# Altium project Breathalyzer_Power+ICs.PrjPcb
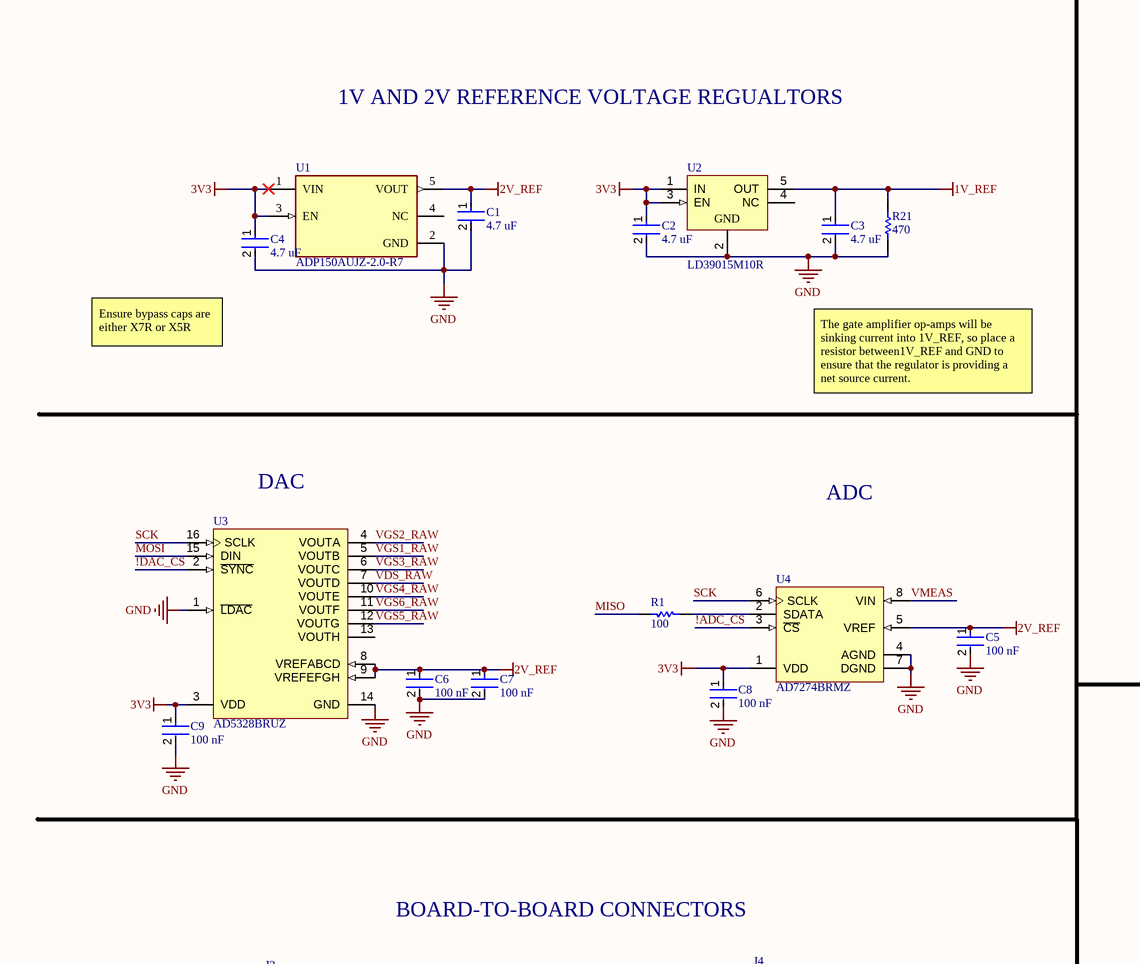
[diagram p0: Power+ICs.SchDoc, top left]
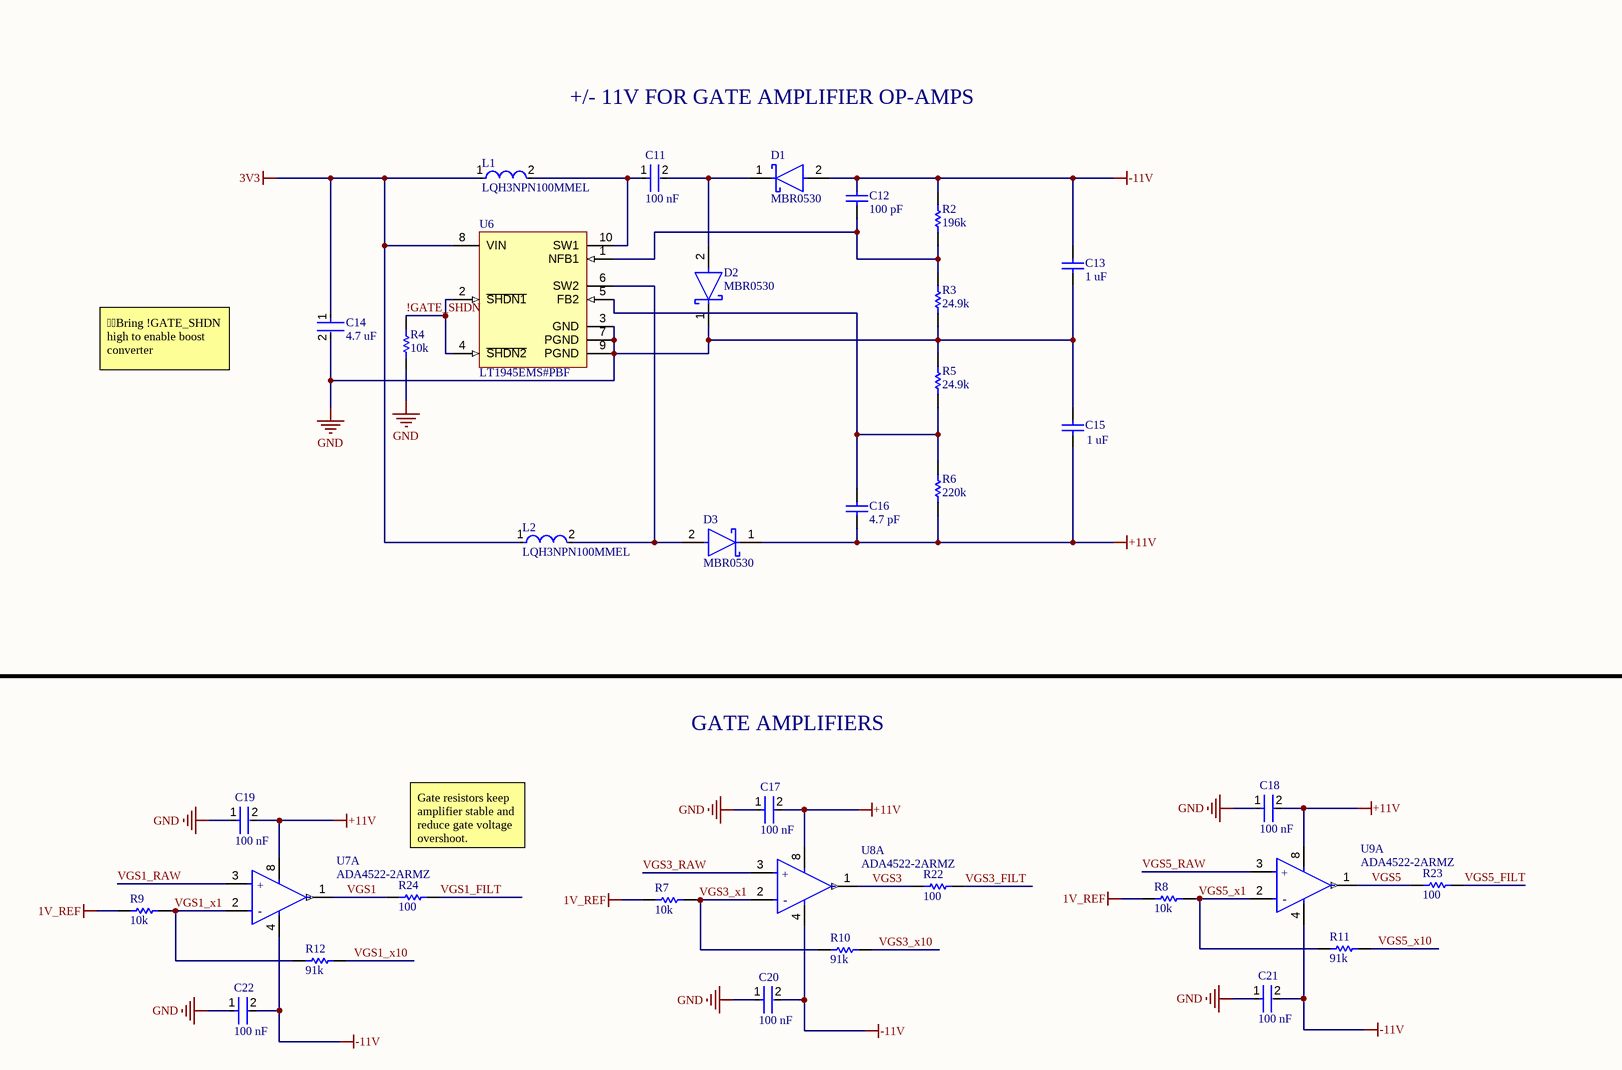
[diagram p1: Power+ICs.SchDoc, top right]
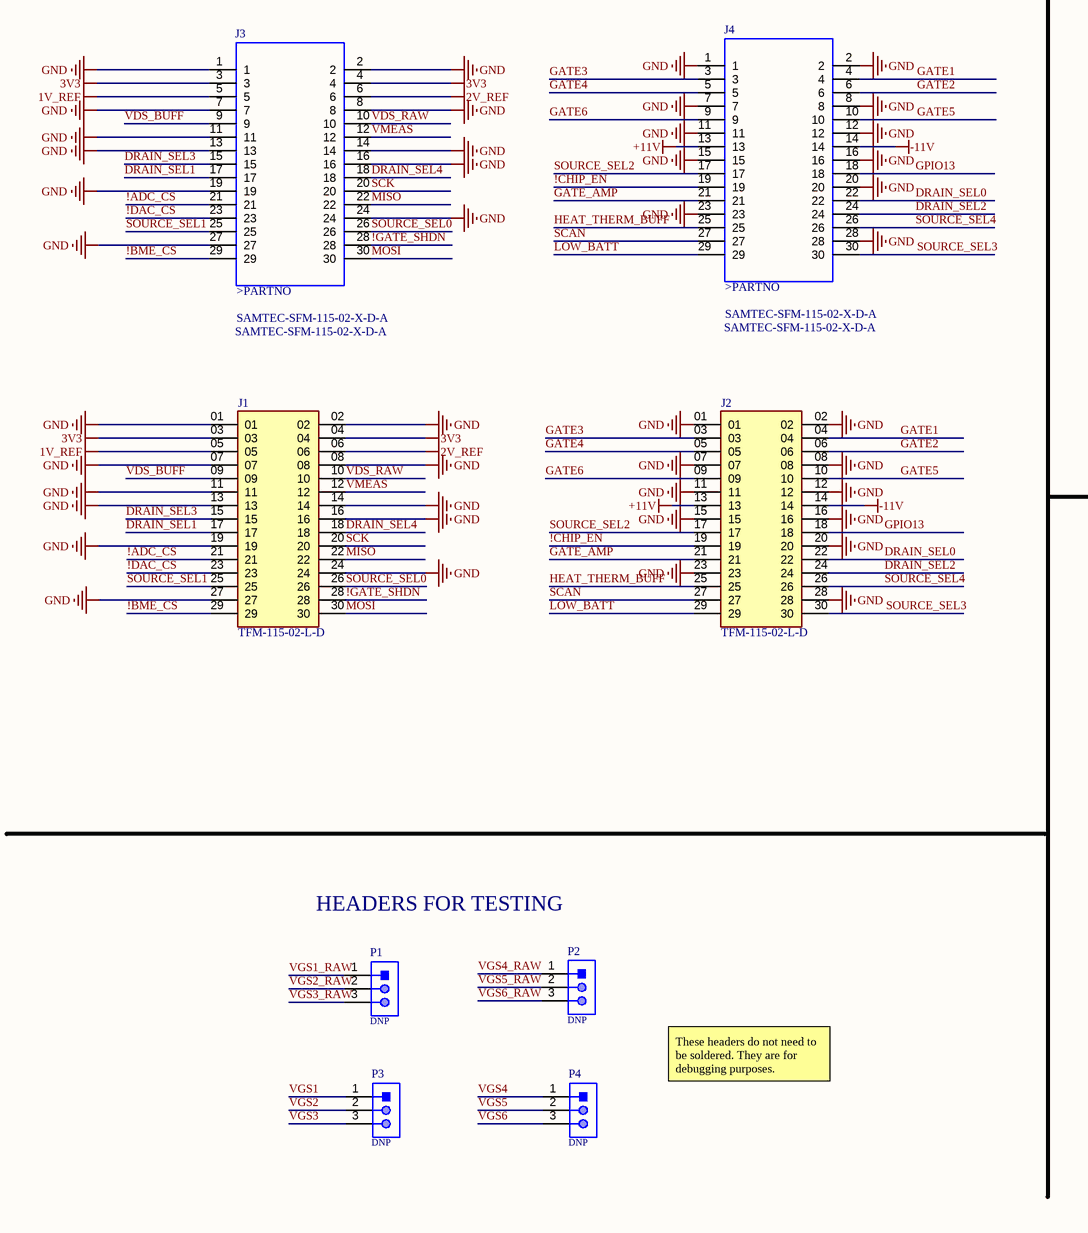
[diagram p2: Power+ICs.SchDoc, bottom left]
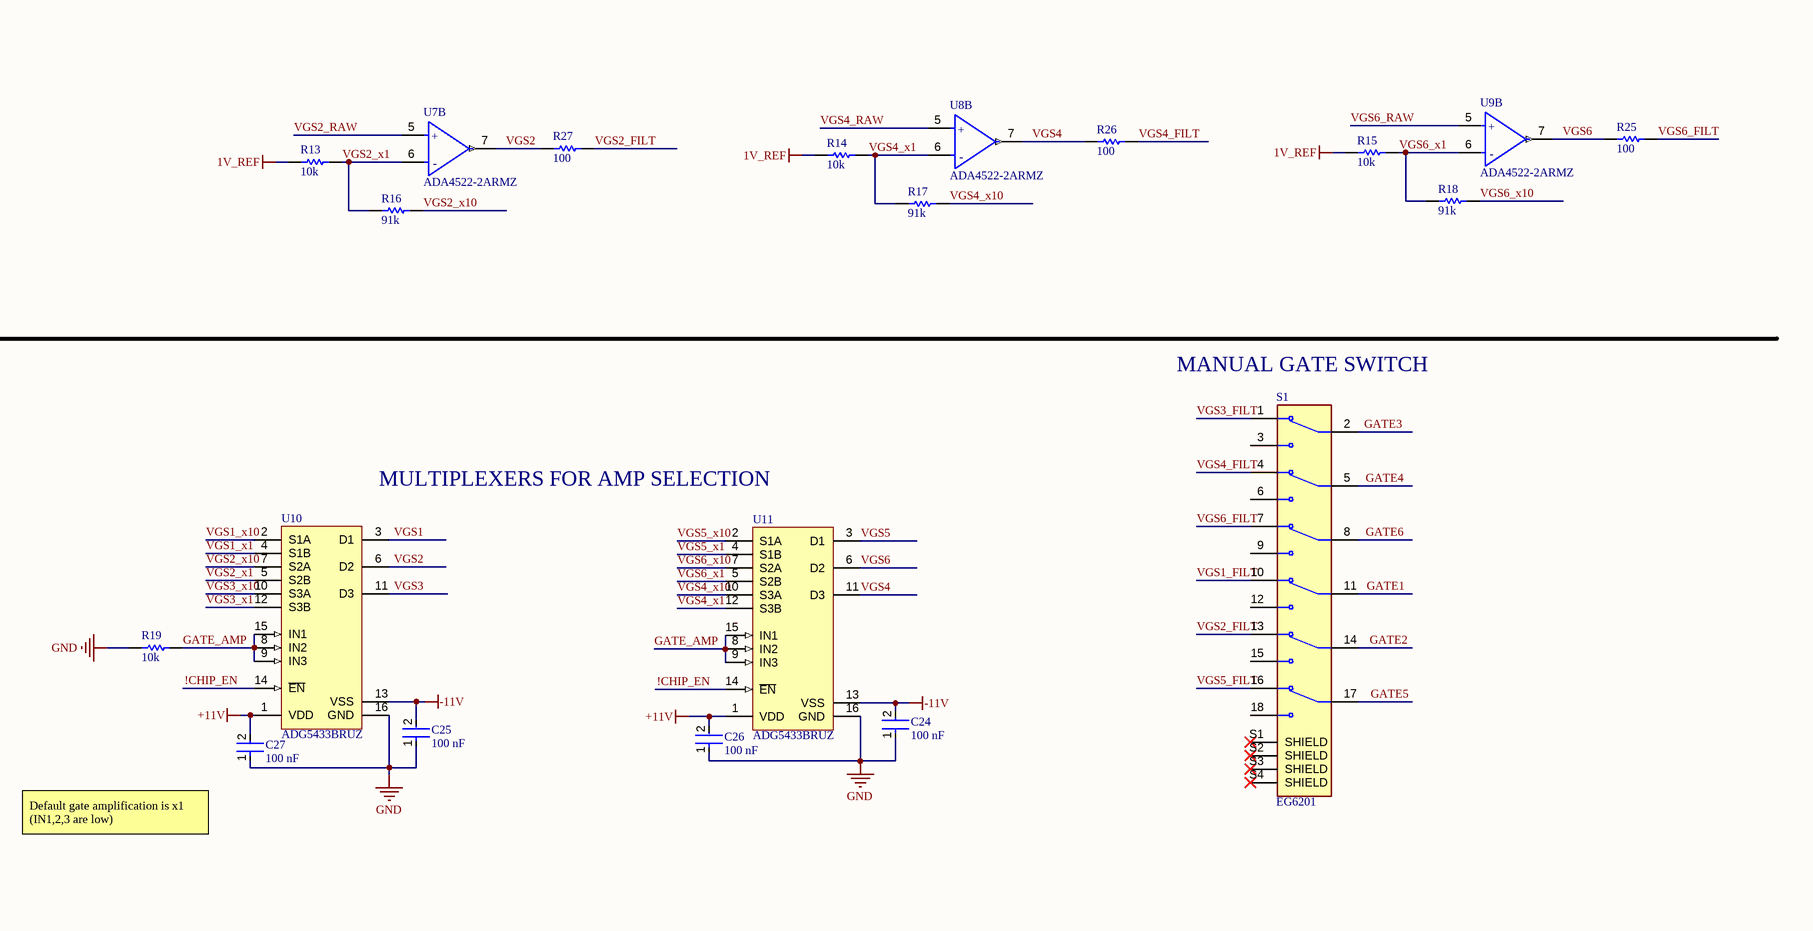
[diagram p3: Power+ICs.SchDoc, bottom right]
CAGE_CODE: ?????; CONTRACT_NUMBER: <CONTRACT NO>; DOC_NO_ASSY_DWG: <ASSY DWG NO>; DOC_NO_BOM: <BOM DOC NO>; DOC_NO_FAB_DWG: <FAB DWG NO>; DOC_NO_SCH_DWG: <SCH DWG NO>; PCB_2_DEC_TOL: +/-.01; PCB_3_DEC_TOL: +/-.010; PCB_ANG_TOL: +/-1/2; PCB_ASSEMBLY_NO: <PCB ASSY NO>; PCB_CHECKER: - -----; PCB_CHECKER_APP_DATE: --/--/----; PCB_DESIGNER: - -----; PCB_DESIGNER_APP_DATE: --/--/----; PCB_DWG_NO: <PCB DWG NO>; PCB_ENGINEER: - -----; PCB_ENGINEER_APP_DATE: --/--/----; PCB_PART_NUMBER: <PCB PN>; PCB_REV: A; SCH_REV: A
1 sheet, 75 parts. Net scope: global (net labels, ports and power ports of the same name join across sheets).
Board file: PCB1.PcbDoc

## Sheet Power+ICs.SchDoc
size 558 x 431 mm; SheetNumber: 1; SheetTotal: 1; ENG_APP_DATE: --/--/--; DSN_APP_DATE: --/--/--; CHK_APP_DATE: --/--/--

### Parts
C1  4.7 uF  [FP-C0805C475K3PACTU-MFG]
C2  4.7 uF  [FP-C0805C475K3PACTU-MFG]
C3  4.7 uF  [FP-C0805C475K3PACTU-MFG]
C4  4.7 uF  [FP-C0805C475K3PACTU-MFG]
C5  100 nF  [FP-C0805C-DN-MFG]
C6  100 nF  [FP-C0805C-DN-MFG]
C7  100 nF  [FP-C0805C-DN-MFG]
C8  100 nF  [FP-C0805C-DN-MFG]
C9  100 nF  [FP-C0805C-DN-MFG]
C11  100 nF  [FP-C0805C-DN-MFG]
C12  100 pF  [CAPC2013X140X50ML20T25]
C13  1 uF  [CAPC3216X110X50LL20T25]
C14  4.7 uF  [FP-C0805C475K3PACTU-MFG]
C15  1 uF  [CAPC3216X110X50LL20T25]
C16  4.7 pF  [CAPC2013X71X50ML20T25]
C17  100 nF  [FP-C0805C-DN-MFG]
C18  100 nF  [FP-C0805C-DN-MFG]
C19  100 nF  [FP-C0805C-DN-MFG]
C20  100 nF  [FP-C0805C-DN-MFG]
C21  100 nF  [FP-C0805C-DN-MFG]
C22  100 nF  [FP-C0805C-DN-MFG]
C24  100 nF  [FP-C0805C-DN-MFG]
C25  100 nF  [FP-C0805C-DN-MFG]
C26  100 nF  [FP-C0805C-DN-MFG]
C27  100 nF  [FP-C0805C-DN-MFG]
D1  MBR0530  [FP-425-04-MFG]
D2  MBR0530  [FP-425-04-MFG]
D3  MBR0530  [FP-425-04-MFG]
J1  TFM-115-02-L-D  [SAMTEC_TFM-115-02-L-D]
J2  TFM-115-02-L-D  [SAMTEC_TFM-115-02-L-D]
J3  SAMTEC-SFM-115-02-X-D-A  [SAMTEC-SFM-115-02-X-D-A]
J4  SAMTEC-SFM-115-02-X-D-A  [SAMTEC-SFM-115-02-X-D-A]
L1  LQH3NPN100MMEL  [FP-LQH3NPH_ME-MFG]
L2  LQH3NPN100MMEL  [FP-LQH3NPH_ME-MFG]
P1  DNP  [61300311021]
P2  DNP  [61300311021]
P3  DNP  [61300311021]
P4  DNP  [61300311021]
R1  100  [RESC2013X50X30LL20T20]
R2  196k  [RESC2013X50X30LL20T20]
R3  24.9k  [RESC2013X70X40LL20T20]
R4  10k  [RESC2013X60X35NL10T20]
R5  24.9k  [RESC2013X70X40LL20T20]
R6  220k  [RESC2013X70X40ML20T20]
R7  10k  [RESC2013X60X35NL10T20]
R8  10k  [RESC2013X60X35NL10T20]
R9  10k  [RESC2013X60X35NL10T20]
R10  91k  [RESC2013X60X35ML10T20]
R11  91k  [RESC2013X60X35ML10T20]
R12  91k  [RESC2013X60X35ML10T20]
R13  10k  [RESC2013X60X35NL10T20]
R14  10k  [RESC2013X60X35NL10T20]
R15  10k  [RESC2013X60X35NL10T20]
R16  91k  [RESC2013X60X35ML10T20]
R17  91k  [RESC2013X60X35ML10T20]
R18  91k  [RESC2013X60X35ML10T20]
R19  10k  [RESC2013X60X35NL10T20]
R21  470  [RESC2013X70X40ML20T20]
R22  100  [RESC2013X50X30LL20T20]
R23  100  [RESC2013X50X30LL20T20]
R24  100  [RESC2013X50X30LL20T20]
R25  100  [RESC2013X50X30LL20T20]
R26  100  [RESC2013X50X30LL20T20]
R27  100  [RESC2013X50X30LL20T20]
S1  EG6201  [SW_EG6201]
U1  ADP150AUJZ-2.0-R7  [FP-UJ-5-IPC_B]
U2  LD39015M10R  [SOT23-5L_M]
U3  AD5328BRUZ  [RU-16_L]
U4  AD7274BRMZ  [RM-8_N]
U6  LT1945EMS#PBF  [LT-MS-10_N]
U7  ADA4522-2ARMZ  [FP-RM-8-IPC_C]  (parts A,B of 2)
U8  ADA4522-2ARMZ  [FP-RM-8-IPC_C]  (parts A,B of 2)
U9  ADA4522-2ARMZ  [FP-RM-8-IPC_C]  (parts A,B of 2)
U10  ADG5433BRUZ  [ADI-RU-16_N]
U11  ADG5433BRUZ  [ADI-RU-16_N]

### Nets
1V_REF: C3.1 J1.05 J3.5 R7.2 R8.2 R9.2 R13.2 R14.2 R15.2 R21.2 U2.5(OUT)
2V_REF: C1.1 C5.1 C6.1 C7.1 J1.06 J3.6 U1.5(VOUT) U3.8(VREFABCD) U3.9(VREFEFGH) U4.5(VREF)
3V3: C2.1 C4.1 C8.1 C9.1 C14.1 J1.03 J1.04 J3.3 J3.4 L1.1 L2.1 U1.1(VIN) U1.3(EN) U2.1(IN) U2.3(EN) U3.3(VDD) U4.1(VDD) U6.8(VIN)
+11V: C15.1 C16.1 C17.2 C18.2 C19.2 C26.2 C27.2 D3.1(C) J2.13 J4.13 R6.1 U7.8(V+) U8.8(V+) U9.8(V+) U10.1(VDD) U11.1(VDD)
-11V: C12.1 C13.2 C20.2 C21.2 C22.2 C24.2 C25.2 D1.2(A) J2.14 J4.14 R2.2 U7.4(V-) U8.4(V-) U9.4(V-) U10.13(VSS) U11.13(VSS)
GND: C1.2 C2.2 C3.2 C4.2 C5.2 C6.2 C7.2 C8.2 C9.2 C13.1 C14.2 C15.2 C17.1 C18.1 C19.1 C20.1 C21.1 C22.1 C24.1 C25.1 C26.1 C27.1 D2.1(C) J1.01 J1.02 J1.07 J1.08 J1.11 J1.13 J1.14 J1.16 J1.19 J1.24 J1.27 J2.01 J2.02 J2.07 J2.08 J2.11 J2.12 J2.15 J2.16 J2.20 J2.23 J2.28 J3.1 J3.2 J3.7 J3.8 J3.11 J3.13 J3.14 J3.16 J3.19 J3.24 J3.27 J4.1 J4.2 J4.7 J4.8 J4.11 J4.12 J4.15 J4.16 J4.20 J4.23 J4.28 R3.1 R4.1 R5.2 R19.2 R21.1 U1.2(GND) U2.2(GND) U3.1(~{LDAC}) U3.14(GND) U4.4(AGND) U4.7(DGND) U6.3(GND) U6.7(PGND) U6.9(PGND) U10.16(GND) U11.16(GND)
!ADC_CS: J1.21 J3.21 U4.3(~{CS})
!BME_CS: J1.29 J3.29
!CHIP_EN: J2.19 J4.19 U10.14(~{EN}) U11.14(~{EN})
!DAC_CS: J1.23 J3.23 U3.2(~{SYNC})
!GATE_SHDN: J1.28 J3.28 R4.2 U6.2(~{SHDN1}) U6.4(~{SHDN2})
DRAIN_SEL0: J2.22 J4.22
DRAIN_SEL1: J1.17 J3.17
DRAIN_SEL2: J2.24 J4.24
DRAIN_SEL3: J1.15 J3.15
DRAIN_SEL4: J1.18 J3.18
GATE1: J2.04 J4.4 S1.11(COM4)
GATE2: J2.06 J4.6 S1.14(COM5)
GATE3: J2.03 J4.3 S1.2(COM1)
GATE4: J2.05 J4.5 S1.5(COM2)
GATE5: J2.10 J4.10 S1.17(COM6)
GATE6: J2.09 J4.9 S1.8(COM3)
GATE_AMP: J2.21 J4.21 R19.1 U10.8(IN2) U10.9(IN3) U10.15(IN1) U11.8(IN2) U11.9(IN3) U11.15(IN1)
GPIO13: J2.18 J4.18
HEAT_THERM_BUFF: J2.25 J4.25
LOW_BATT: J2.29 J4.29
MISO: J1.22 J3.22 R1.2
MOSI: J1.30 J3.30 U3.15(DIN)
SCAN: J2.27 J4.27
SCK: J1.20 J3.20 U3.16(SCLK) U4.6(SCLK)
SOURCE_SEL0: J1.26 J3.26
SOURCE_SEL1: J1.25 J3.25
SOURCE_SEL2: J2.17 J4.17
SOURCE_SEL3: J2.30 J4.30
SOURCE_SEL4: J2.26 J4.26
VDS_BUFF: J1.09 J3.9
VDS_RAW: J1.10 J3.10 U3.7(VOUTD)
VGS1: P3.1 R24.1 U7.1(OUT_A) U10.3(D1)
VGS1_FILT: R24.2 S1.10(NC4)
VGS1_RAW: P1.1 U3.5(VOUTB) U7.3(+IN_A)
VGS1_x1: R9.1 R12.1 U7.2(-IN_A) U10.4(S1B)
VGS1_x10: R12.2 U10.2(S1A)
VGS2: P3.2 R27.1 U7.7(OUT_B) U10.6(D2)
VGS2_FILT: R27.2 S1.13(NC5)
VGS2_RAW: P1.2 U3.4(VOUTA) U7.5(+IN_B)
VGS2_x1: R13.1 R16.1 U7.6(-IN_B) U10.5(S2B)
VGS2_x10: R16.2 U10.7(S2A)
VGS3: P3.3 R22.1 U8.1(OUT_A) U10.11(D3)
VGS3_FILT: R22.2 S1.1(NC1)
VGS3_RAW: P1.3 U3.6(VOUTC) U8.3(+IN_A)
VGS3_x1: R7.1 R10.1 U8.2(-IN_A) U10.12(S3B)
VGS3_x10: R10.2 U10.10(S3A)
VGS4: P4.1 R26.1 U8.7(OUT_B) U11.11(D3)
VGS4_FILT: R26.2 S1.4(NC2)
VGS4_RAW: P2.1 U3.10(VOUTE) U8.5(+IN_B)
VGS4_x1: R14.1 R17.1 U8.6(-IN_B) U11.12(S3B)
VGS4_x10: R17.2 U11.10(S3A)
VGS5: P4.2 R23.1 U9.1(OUT_A) U11.3(D1)
VGS5_FILT: R23.2 S1.16(NC6)
VGS5_RAW: P2.2 U3.12(VOUTG) U9.3(+IN_A)
VGS5_x1: R8.1 R11.1 U9.2(-IN_A) U11.4(S1B)
VGS5_x10: R11.2 U11.2(S1A)
VGS6: P4.3 R25.1 U9.7(OUT_B) U11.6(D2)
VGS6_FILT: R25.2 S1.7(NC3)
VGS6_RAW: P2.3 U3.11(VOUTF) U9.5(+IN_B)
VGS6_x1: R15.1 R18.1 U9.6(-IN_B) U11.5(S2B)
VGS6_x10: R18.2 U11.7(S2A)
VMEAS: J1.12 J3.12 U4.8(VIN)
NetC11_1: C11.1 L1.2 U6.10(SW1)
NetC11_2: C11.2 D1.1(C) D2.2(A)
NetC12_2: C12.2 R2.1 R3.2 U6.1(NFB1)
NetC16_2: C16.2 R5.1 R6.2 U6.5(FB2)
NetD3_2: D3.2(A) L2.2 U6.6(SW2)
NetR1_1: R1.1 U4.2(SDATA)

Not connected (* = marked no-connect by the designer): S1 3(NO1) 6(NO2) 9(NO3) 12(NO4) 15(NO5) 18(NO6) S1(SHIELD)* S2(SHIELD)* S3(SHIELD)* S4(SHIELD)*; U1 4(NC); U2 4(NC); U3 13(VOUTH)

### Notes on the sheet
- 1V AND 2V REFERENCE VOLTAGE REGUALTORS
- +/- 11V FOR GATE AMPLIFIER OP-AMPS
- Ensure bypass caps are either X7R or X5R
- Bring !GATE_SHDN high to enable boost converter
- The gate amplifier op-amps will be sinking current into 1V_REF, so place a resistor between1V_REF and GND to ensure that the regulator is providing a net source current.
- (near U3) DAC
- ADC
- GATE AMPLIFIERS
- (near R24) Gate resistors keep amplifier stable and reduce gate voltage overshoot.
- BOARD-TO-BOARD CONNECTORS
- (near S1) MANUAL GATE SWITCH
- MULTIPLEXERS FOR AMP SELECTION
- HEADERS FOR TESTING
- Default gate amplification is x1 (IN1,2,3 are low)
- These headers do not need to be soldered. They are for debugging purposes.

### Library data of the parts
C1-C4 C14 = CMP-2007-01010-2: CAP CER 4.7UF 25V X5R 0805; Tolerance: 10%; Dielectric Material: Ceramic; Dissipation Factor: 5%
C5-C9 C11 C17-C22 C24-C27 = CMP-2007-00279-2: CAP CER 0.1UF 50V X7R 0805; Manufacturer Part Number: C0805C104K5RACTU; Manufacturer: KEMET; Value: 0.10 μF; Tolerance: 0.1; Temperature Coefficient: 30ppm/°C; Material: Ceramic
C12 = CMP-2007-04713-1: 08055C101KAT2A; Manufacturer: AVX Interconnect / Elco
C13 C15 = CMP-2000-06011-1: C1206C105K5RACTU; Manufacturer: Kemet; Case Height: 1mm; Dielectric: X7R; Voltage Rating: 50V; Capacitance: 1uF; Temperature Coefficient / Code: +/-15%; Case Length: 3.2mm; Case Width: 1.6mm; Type: SMDMLCCX7R6.3-250VDCCommericalGrade; Tolerance: 10%; Class: Class1; Capacitance - nF: 1000nF
C16 = CMP-1036-00549-2: 08055A4R7CAT2A; Manufacturer: AVX Interconnect / Elco
D1-D3 = CMP-2000-05113-2: DIODE SCHOTTKY 30V 500MA SOD123; Polarity: Standard; Max Reverse Leakage Current: 130uA; Forward Voltage: 430mV; Element Configuration: Single; Peak Non-Repetitive Surge Current: 5.5A
J1 J2 = TFM-115-02-L-D: MF: Samtec Inc.; System: Connector
J3 J4 = SAMTEC-SFM-115-02-X-D-A: System: Connector; MF: Samtec Inc.
L1 L2 = CMP-06042-002074-1: Wire Wound Ferrite Inductor for Power Lines 10μH ±20% 0.228Ω 1280mA 1212; Current Rating: 1.28A; DC Resistance (DCR): 228mR; Inductance: 10uH; Saturation Current: 810mA; Self Resonant Frequency: 20MHz; Shielding: Shielded; Test Frequency: 1MHz
P1-P4 = CMP-1502-01061-1: THT Angled Pin Header WR-PHD, Pitch 2.54 mm, Single Row, 3 pins; Manufacturer: Wurth Elektronik; Pitch: 2.54mm; Contact Resistance: 20mOhm; Gender: Male; Pin Number: 3; Rated Current: 3A; Working Voltage: 250VAC; Withstanding Voltage: 500VAC
R1 R22-R27 = CMP-2001-04901-1: Manufacturer: Vishay Dale; Part Number: CRCW0805100RFKEA
R2 = CMP-2001-04310-1: Manufacturer: Vishay Dale; Part Number: CRCW0805196KFKEA
R3 R5 = CMP-2001-00073-1: Part Number: ERJ-6ENF2492V; Manufacturer: Panasonic
R4 R7-R9 R13-R15 R19 = CMP-1659-00013-4: Chip Resistor, 10 KOhm, +/- 1%, 0.125 W, -55 to 155 degC, 0805 (2012 Metric), RoHS, Tape and Reel; Manufacturer: Yageo; Voltage Rating: 150 V
R6 = CMP-2001-00522-1: Part Number: ERJ6ENF2203V; Manufacturer: Panasonic
R10-R12 R16-R18 = CMP-2001-01407-1: Part Number: RC0805JR-0791KL; Manufacturer: Yageo
R21 = CMP-2001-00549-5: Chip Resistor, 470 Ohm, +/- 1%, 0.125 W, -55 to 155 degC, 0805 (2012 Metric), RoHS, Tape and Reel; Manufacturer: Panasonic; Voltage Rating: 150 V
S1 = EG6201: Slide Switch 6PDT Through Hole, Right Angle; MF: E-Switch
U1 = CMP-09138-000207-1: IC REG LINEAR 2V 150MA 5TSOT; Dropout Voltage: 105mV; Output Configuration: Positive; Max Input Voltage: 5.5V; Max Supply Current: 320uA; Output Type: Fixed; Min Current Limit: 190mA; Accuracy: 1%; Operating Supply Current: 10uA; Number of Regulators: 1; Quiescent Current: 22uA; Power Supply Rejection Ratio (PSRR): 70dB; Min Input Voltage: 2.2V
U2 = CMP-0244-00345-1: 150 mA Low Quiescent Current Low Noise Voltage Regulator, 1.0V, 5-Pin SOT-23, Tape and Reel
U3 = CMP-0318-02011-2: Octal 12-Bit Voltage Output Digital-to-Analog Converter, 2.5 to 5.5 V, -40 to +125 degC, RU-16, Pb-Free, Tube; Generic Part Number: AD5328; Manufacturer: Analog Devices; Settling Time: 6Âµs; Op Pwr Diss: 5mW; Max V+: 5.5V; Single Supply: Yes; Resolution (Bits): 12; # DAC Outputs: 8
U4 = CMP-0313-01921-2: Single 12-Bit Analog-to-Digital Converter with Serial, SPI Interface, 3MSPS, -40 to +125 degC, RM-8, Pb-Free, Tube; Generic Part Number: AD7274; Manufacturer: Analog Devices; Throughput Rate (SPS): 3M; Channels: 1; Interface: Ser, SPI; Resolution (Bits): 12
U6 = CMP-0478-00153-1: Dual Micropower DC/DC Converter with Positive and Negative Outputs, 1.2 to 15 V Vin, 10-pin SOP (MS-10), -40 to 85 degC, Pb-Free; Manufacturer: Linear Technology; Number of Outputs: 2; Vin Max(V): 15; Vin Min(V): 1.2
U7-U9 = CMP-09116-000003-2: IC OPAMP ZERO-DRIFT 2 CIRC 8MSOP; Max Dual Supply Voltage: 27.5V; Power Supply Rejection Ratio (PSRR): 150dB; Operating Supply Current: 830uA; Max Supply Voltage: 55V; Min Dual Supply Voltage: 2.25V; Input Bias Current: 50pA; Gain Bandwidth Product: 2.7MHz; Voltage Gain: 137dB; Common Mode Rejection Ratio: 140dB; Slew Rate: 1.7V/µs; Input Offset Voltage (Vos): 1.5uV; Output Current per Channel: 32mA; Min Supply Voltage: 4.5V
U10 U11 = CMP-0794-00021-1: High Voltage Latch-Up Proof, Triple SPDT Switches, 12.5 Ohm Ron, 16-pin SOP (RU-16), Tube; Manufacturer: Analog Devices; Ron (ohms): 13.5, 12.5, 26, 14.5; Max Pos Supply: +40V; Max Neg Supply: -22V; # Sw Functions: 3; t ON: 160ns, 152ns, 228ns, 176ns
